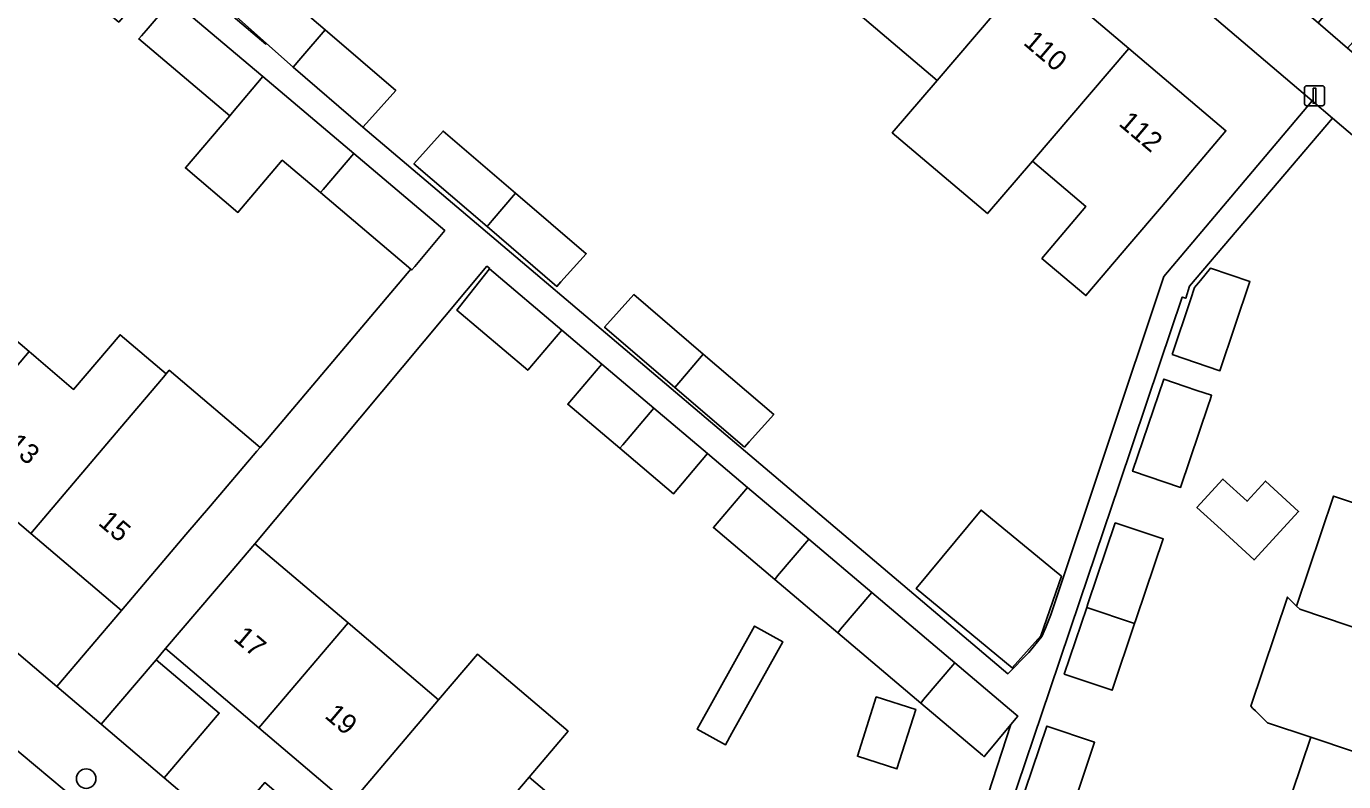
# Model space of a CAD drawing. Extents: x 162523 to 163266, y 381230 to 382050.
# Drawn here: x 163155.8 to 163221.9, y 381622.8 to 381660.7 of the extents above; entities that cross this region are included whole.
import ezdxf

# ---------------------------------------------------------------- set-up
doc = ezdxf.new("R2010")
doc.units = 0
for name, color, linetype in [('IMGEO_Boom', 7, 'Continuous'), ('IMGEO_Erf', 7, 'Continuous'), ('IMGEO_Grasland_overig', 7, 'Continuous'), ('IMGEO_Lichtmast', 7, 'Continuous'), ('IMGEO_Pand', 7, 'Continuous'), ('IMGEO_Pand_nummerreeks', 7, 'Continuous'), ('IMGEO_Rijbaan_lokaal_open', 7, 'Continuous'), ('IMGEO_Voetpad_open', 7, 'Continuous')]:
    doc.layers.add(name, color=color, linetype=linetype)

msp = doc.modelspace()

# ---------------------------------------------------------------- linework, layer by layer
at = {"layer": 'IMGEO_Boom'}
msp.add_circle((163158.816, 381622.902), 0.489, dxfattribs=at)
at = {"layer": 'IMGEO_Erf'}
for points in [[(163140.97, 381682.758), (163159.202, 381667.12), (163167.841, 381659.784), (163167.869, 381659.815), (163165.748, 381661.71), (163167.33, 381663.48), (163170.81, 381660.497), (163174.354, 381657.457), (163173.044, 381655.991), (163172.708, 381655.616), (163205.068, 381628.172), (163206.134, 381629.238), (163206.785, 381630.042), (163206.97, 381630.457), (163207.227, 381631.126), (163212.9, 381648.115), (163220.342, 381656.94), (163142.194, 381723.423)], [(163151.406, 381648.209), (163155.954, 381644.343), (163158.186, 381642.446), (163160.518, 381645.191), (163162.834, 381643.222), (163162.99, 381643.405), (163167.545, 381639.532), (163175.12, 381648.487), (163170.58, 381652.326), (163168.654, 381653.955), (163166.431, 381651.337), (163163.797, 381653.565), (163166.019, 381656.183), (163161.457, 381660.042), (163161.596, 381660.206), (163161.82, 381660.47), (163163.132, 381662.014), (163162.131, 381662.862), (163160.455, 381660.889), (163156.896, 381663.899), (163153.342, 381666.904)], [(163206.364, 381663.627), (163211.148, 381659.567), (163216.021, 381655.432), (163212.786, 381651.621), (163211.199, 381649.751), (163208.995, 381647.155), (163206.79, 381649.026), (163208.993, 381651.623), (163206.306, 381653.903), (163204.053, 381651.276), (163199.275, 381655.331), (163201.522, 381657.963), (163196.777, 381661.991)], [(163237.57, 381642.272), (163221.374, 381656.062), (163214.196, 381647.625), (163214.001, 381647.024), (163213.833, 381647.081), (163212.71, 381643.748), (163210.663, 381637.676), (163208.69, 381631.823), (163207.189, 381627.369), (163205.166, 381621.366)], [(163199.319, 381607.452), (163205.221, 381625.613), (163203.918, 381624.045), (163203.885, 381624.005), (163203.802, 381624.076), (163200.704, 381626.699), (163196.538, 381630.229), (163193.375, 381632.907), (163190.301, 381635.511), (163192.013, 381637.526), (163190.008, 381639.224), (163188.297, 381637.209), (163185.603, 381639.491), (163182.989, 381641.705), (163184.7, 381643.721), (163182.692, 381645.421), (163180.982, 381643.406), (163177.413, 381646.429), (163177.549, 381646.6), (163179.062, 381648.496), (163179.074, 381648.511), (163178.931, 381648.633), (163167.279, 381634.698), (163171.959, 381630.718), (163176.507, 381626.851), (163178.456, 381629.146), (163183.004, 381625.278), (163181.055, 381622.983), (163185.603, 381619.116)], [(163151.263, 381632.684), (163157.339, 381627.523), (163160.588, 381631.345), (163156.035, 381635.214), (163151.486, 381639.08)], [(163220.278, 381624.983), (163218.109, 381625.71), (163217.509, 381626.301), (163217.378, 381626.43), (163217.269, 381626.537), (163219.109, 381632.022), (163219.218, 381631.915), (163219.571, 381631.567), (163221.424, 381637.086), (163223.462, 381636.403)], [(163218.394, 381619.371), (163220.278, 381624.983)]]:
    msp.add_lwpolyline(points, dxfattribs=at)
for points in [[(163183.914, 381649.259), (163182.647, 381647.842), (163182.447, 381647.618), (163178.937, 381650.628), (163175.265, 381653.776), (163176.733, 381655.417), (163180.368, 381652.301)], [(163213.316, 381644.197), (163214.242, 381646.943), (163214.452, 381647.569), (163214.743, 381647.923), (163215.242, 381648.531), (163217.229, 381647.861), (163215.721, 381643.386)], [(163193.323, 381641.191), (163192.098, 381639.82), (163191.856, 381639.55), (163188.362, 381642.546), (163184.835, 381645.57), (163186.303, 381647.211), (163189.79, 381644.22)], [(163213.747, 381637.529), (163211.34, 381638.336), (163212.899, 381642.961), (163213.97, 381642.6), (163214.563, 381642.4), (163215.304, 381642.15), (163215.226, 381641.918), (163215.15, 381641.691)], [(163215.775, 381635.411), (163214.567, 381636.522), (163215.874, 381637.943), (163217.081, 381636.832), (163218.008, 381637.84), (163219.671, 381636.312), (163217.437, 381633.883)], [(163207.411, 381633.352), (163207.761, 381633.063), (163206.733, 381630.076), (163205.297, 381628.462), (163200.477, 381632.448), (163203.737, 381636.391)], [(163211.441, 381630.688), (163210.312, 381627.339), (163207.907, 381628.149), (163209.034, 381631.494), (163209.099, 381631.686), (163210.467, 381635.745), (163212.874, 381634.938), (163211.54, 381630.983), (163211.506, 381630.88)], [(163192.366, 381630.559), (163193.789, 381629.764), (163191.23, 381625.182), (163190.902, 381624.596), (163189.479, 381625.391)], [(163176.585, 381617.719), (163172.036, 381621.586), (163167.487, 381625.452), (163162.803, 381629.433), (163162.328, 381628.874), (163165.493, 381626.194), (163162.731, 381622.942), (163165.78, 381620.352), (163167.777, 381622.704), (163173.818, 381617.55), (163171.832, 381615.212), (163174.881, 381612.622), (163176.901, 381615.001), (163182.949, 381609.858), (163180.931, 381607.482), (163184.651, 381604.323), (163186.72, 381602.564), (163191.624, 381598.399), (163194.85, 381602.194), (163190.231, 381606.12), (163185.682, 381609.986), (163181.133, 381613.853)], [(163198.474, 381627.005), (163200.454, 381626.376), (163199.508, 381623.394), (163197.528, 381624.023)], [(163207.981, 381620.422), (163206.547, 381616.169), (163206.45, 381615.881), (163204.044, 381616.689), (163204.172, 381617.067), (163205.574, 381621.229), (163207.027, 381625.539), (163209.433, 381624.732)]]:
    msp.add_lwpolyline(points, close=True, dxfattribs=at)
at = {"layer": 'IMGEO_Grasland_overig'}
msp.add_lwpolyline([(163165.493, 381626.194), (163162.328, 381628.874), (163159.568, 381625.629), (163162.731, 381622.942)], close=True, dxfattribs=at)
at = {"layer": 'IMGEO_Lichtmast'}
for p, q in [((163220.072, 381657.694), (163220.862, 381657.694)), ((163220.862, 381657.694), (163220.072, 381657.694)), ((163219.972, 381656.794), (163219.972, 381657.594)), ((163219.972, 381657.594), (163219.972, 381656.794)), ((163220.962, 381657.594), (163220.962, 381656.794)), ((163220.962, 381656.794), (163220.962, 381657.594)), ((163220.862, 381656.694), (163220.072, 381656.694)), ((163220.072, 381656.694), (163220.862, 381656.694))]:
    msp.add_line(p, q, dxfattribs=at)
msp.add_lwpolyline([(163220.392, 381657.569), (163220.542, 381657.569), (163220.542, 381656.819), (163220.392, 381656.819), (163220.392, 381657.569)], dxfattribs=at)
for centre, start, end in [((163220.072, 381657.594), 90, 180), ((163220.072, 381657.594), 90, 180), ((163220.862, 381657.594), 0, 90), ((163220.862, 381657.594), 360, 90), ((163220.072, 381656.794), 180, 270), ((163220.072, 381656.794), 180, 270), ((163220.862, 381656.794), 270, 0), ((163220.862, 381656.794), 270, 0)]:
    msp.add_arc(centre, 0.1, start, end, dxfattribs=at)
at = {"layer": 'IMGEO_Pand'}
for points in [[(163196.777, 381661.991), (163201.522, 381657.963), (163206.364, 381663.627), (163201.621, 381667.653)], [(163206.306, 381653.903), (163211.148, 381659.567), (163206.364, 381663.627), (163201.522, 381657.963), (163199.275, 381655.331), (163204.053, 381651.276)], [(163167.869, 381659.815), (163169.205, 381658.62), (163169.595, 381659.076), (163170.81, 381660.497), (163167.33, 381663.48), (163165.748, 381661.71)], [(163163.132, 381662.014), (163161.82, 381660.47), (163161.596, 381660.206), (163161.457, 381660.042), (163166.019, 381656.183), (163166.159, 381656.348), (163167.691, 381658.152)], [(163170.81, 381660.497), (163169.595, 381659.076), (163169.205, 381658.62), (163172.708, 381655.616), (163173.044, 381655.991), (163174.354, 381657.457)], [(163206.306, 381653.903), (163208.993, 381651.623), (163206.79, 381649.026), (163208.995, 381647.155), (163211.199, 381649.751), (163212.786, 381651.621), (163216.021, 381655.432), (163211.148, 381659.567)], [(163167.691, 381658.152), (163166.159, 381656.348), (163166.019, 381656.183), (163163.797, 381653.565), (163166.431, 381651.337), (163168.654, 381653.955), (163170.58, 381652.326), (163170.72, 381652.49), (163172.249, 381654.291)], [(163178.937, 381650.628), (163179.195, 381650.929), (163180.368, 381652.301), (163176.733, 381655.417), (163175.265, 381653.776)], [(163172.249, 381654.291), (163170.72, 381652.49), (163170.58, 381652.326), (163175.12, 381648.487), (163175.167, 381648.447), (163175.305, 381648.613), (163176.813, 381650.426)], [(163180.368, 381652.301), (163179.195, 381650.929), (163178.937, 381650.628), (163182.447, 381647.618), (163182.647, 381647.842), (163183.914, 381649.259)], [(163179.062, 381648.496), (163177.549, 381646.6), (163177.413, 381646.429), (163180.982, 381643.406), (163182.692, 381645.421)], [(163213.316, 381644.197), (163215.721, 381643.386), (163217.229, 381647.861), (163215.242, 381648.531), (163214.743, 381647.923), (163214.452, 381647.569), (163214.242, 381646.943)], [(163146.937, 381642.946), (163151.486, 381639.08), (163155.954, 381644.343), (163151.406, 381648.209)], [(163188.362, 381642.546), (163188.66, 381642.896), (163189.79, 381644.22), (163186.303, 381647.211), (163184.835, 381645.57)], [(163162.834, 381643.222), (163160.518, 381645.191), (163158.186, 381642.446), (163155.954, 381644.343), (163151.486, 381639.08), (163156.035, 381635.214), (163160.503, 381640.476), (163162.699, 381643.063)], [(163184.7, 381643.721), (163182.989, 381641.705), (163185.603, 381639.491), (163185.746, 381639.66), (163187.314, 381641.506)], [(163189.79, 381644.22), (163188.66, 381642.896), (163188.362, 381642.546), (163191.856, 381639.55), (163192.098, 381639.82), (163193.323, 381641.191)], [(163162.834, 381643.222), (163162.699, 381643.063), (163160.503, 381640.476), (163156.035, 381635.214), (163160.588, 381631.345), (163163.826, 381635.156), (163165.057, 381636.604), (163167.39, 381639.348), (163167.545, 381639.532), (163162.99, 381643.405)], [(163213.97, 381642.6), (163212.899, 381642.961), (163211.34, 381638.336), (163213.747, 381637.529), (163215.15, 381641.691), (163215.226, 381641.918), (163215.304, 381642.15), (163214.563, 381642.4)], [(163190.008, 381639.224), (163187.314, 381641.506), (163185.746, 381639.66), (163185.603, 381639.491), (163188.297, 381637.209)], [(163217.081, 381636.832), (163215.874, 381637.943), (163214.567, 381636.522), (163215.775, 381635.411), (163217.437, 381633.883), (163219.671, 381636.312), (163218.008, 381637.84)], [(163192.013, 381637.526), (163190.301, 381635.511), (163193.375, 381632.907), (163193.52, 381633.078), (163195.086, 381634.923)], [(163230.567, 381634.022), (163224.045, 381636.208), (163223.462, 381636.403), (163221.424, 381637.086), (163219.571, 381631.567), (163219.73, 381631.411), (163222.161, 381630.596), (163228.685, 381628.409)], [(163200.477, 381632.448), (163205.297, 381628.462), (163206.733, 381630.076), (163207.761, 381633.063), (163207.411, 381633.352), (163203.737, 381636.391)], [(163209.034, 381631.494), (163211.441, 381630.688), (163211.506, 381630.88), (163211.54, 381630.983), (163212.874, 381634.938), (163210.467, 381635.745), (163209.099, 381631.686)], [(163167.487, 381625.452), (163171.959, 381630.718), (163167.279, 381634.698), (163166.042, 381633.243), (163162.803, 381629.433)], [(163195.086, 381634.923), (163193.52, 381633.078), (163193.375, 381632.907), (163196.538, 381630.229), (163196.683, 381630.4), (163198.248, 381632.244)], [(163198.248, 381632.244), (163196.683, 381630.4), (163196.538, 381630.229), (163200.704, 381626.699), (163200.85, 381626.871), (163202.416, 381628.714)], [(163228.685, 381628.409), (163222.161, 381630.596), (163219.73, 381631.411), (163219.571, 381631.567), (163219.218, 381631.915), (163219.109, 381632.022), (163217.269, 381626.537), (163217.378, 381626.43), (163217.509, 381626.301), (163218.109, 381625.71), (163220.278, 381624.983), (163226.804, 381622.796)], [(163211.441, 381630.688), (163209.034, 381631.494), (163207.907, 381628.149), (163210.312, 381627.339)], [(163167.487, 381625.452), (163172.036, 381621.586), (163176.507, 381626.851), (163171.959, 381630.718)], [(163189.479, 381625.391), (163190.902, 381624.596), (163191.23, 381625.182), (163193.789, 381629.764), (163192.366, 381630.559)], [(163181.055, 381622.983), (163183.004, 381625.278), (163178.456, 381629.146), (163176.507, 381626.851), (163172.036, 381621.586), (163176.585, 381617.719)], [(163202.416, 381628.714), (163200.85, 381626.871), (163200.704, 381626.699), (163203.802, 381624.076), (163203.885, 381624.005), (163203.918, 381624.045), (163205.221, 381625.613), (163205.574, 381626.039), (163205.154, 381626.394)], [(163197.528, 381624.023), (163199.508, 381623.394), (163200.454, 381626.376), (163198.474, 381627.005)], [(163205.574, 381621.229), (163207.448, 381620.601), (163207.595, 381620.552), (163207.981, 381620.422), (163209.433, 381624.732), (163207.027, 381625.539)], [(163220.278, 381624.983), (163218.394, 381619.371), (163224.923, 381617.183), (163226.804, 381622.796)], [(163185.603, 381619.116), (163181.055, 381622.983), (163176.585, 381617.719), (163181.133, 381613.853)]]:
    msp.add_lwpolyline(points, close=True, dxfattribs=at)
at = {"layer": 'IMGEO_Rijbaan_lokaal_open'}
msp.add_lwpolyline([(163155.947, 381618.976), (163158.315, 381621.734), (163158.107, 381621.91), (163158.194, 381622.012), (163157.973, 381622.156), (163157.707, 381622.339), (163154.829, 381624.748), (163154.677, 381624.892), (163154.343, 381625.343), (163154.207, 381625.235), (163154.129, 381625.302), (163151.866, 381622.506), (163152.117, 381622.4), (163152.423, 381622.195), (163155.719, 381619.322), (163155.878, 381619.093)], close=True, dxfattribs=at)
at = {"layer": 'IMGEO_Voetpad_open'}
for points in [[(163145.337, 381726.7), (163142.194, 381723.423), (163220.342, 381656.94), (163221.374, 381656.062), (163237.57, 381642.272), (163241.66, 381639.009), (163250.252, 381632.117), (163250.367, 381633.129)], [(163237.947, 381646.091), (163227.167, 381655.314), (163222.131, 381659.586), (163220.653, 381660.859), (163207.022, 381672.435), (163206.696, 381672.73), (163205.174, 381674.003), (163201.925, 381676.775), (163191.471, 381685.659), (163189.947, 381686.961), (163186.391, 381689.994), (163176.258, 381698.624), (163174.752, 381699.935), (163164.938, 381708.239)], [(163159.568, 381625.629), (163157.339, 381627.523), (163151.263, 381632.684), (163148.238, 381635.254), (163139.137, 381642.985), (163136.111, 381645.555), (163133.063, 381648.145), (163127.011, 381653.286), (163123.962, 381655.875), (163120.755, 381658.6), (163119.655, 381659.534), (163118.125, 381660.834), (163117.58, 381661.297), (163106.497, 381670.706), (163101.218, 381675.181), (163100.456, 381675.828), (163098.283, 381673.302)], [(163205.166, 381621.366), (163207.189, 381627.369), (163208.69, 381631.823), (163210.663, 381637.676), (163212.71, 381643.748), (163213.833, 381647.081), (163214.001, 381647.024), (163214.196, 381647.625), (163221.374, 381656.062), (163220.342, 381656.94), (163212.9, 381648.115), (163207.227, 381631.126), (163206.97, 381630.457), (163206.785, 381630.042), (163206.134, 381629.238), (163205.068, 381628.172), (163172.708, 381655.616), (163169.205, 381658.62), (163167.869, 381659.815), (163167.841, 381659.784), (163159.202, 381667.12)], [(163163.132, 381662.014), (163167.691, 381658.152), (163172.249, 381654.291), (163176.813, 381650.426), (163175.305, 381648.613), (163175.167, 381648.447), (163175.12, 381648.487), (163167.545, 381639.532), (163167.39, 381639.348), (163165.057, 381636.604), (163163.826, 381635.156), (163160.588, 381631.345), (163157.339, 381627.523), (163159.568, 381625.629), (163162.328, 381628.874), (163162.803, 381629.433), (163166.042, 381633.243), (163167.279, 381634.698), (163178.931, 381648.633), (163179.074, 381648.511), (163179.062, 381648.496), (163182.692, 381645.421), (163184.7, 381643.721), (163187.314, 381641.506), (163190.008, 381639.224), (163192.013, 381637.526), (163195.086, 381634.923), (163198.248, 381632.244), (163202.416, 381628.714), (163205.154, 381626.394), (163205.574, 381626.039), (163205.221, 381625.613), (163199.319, 381607.452)], [(163153.965, 381627.453), (163154.089, 381626.115), (163154.343, 381625.343), (163154.677, 381624.892), (163154.829, 381624.748), (163157.707, 381622.339), (163157.973, 381622.156), (163158.194, 381622.012)], [(163204.493, 381582.322), (163215.616, 381577.85), (163215.721, 381578.005), (163218.125, 381581.561), (163213.504, 381583.11), (163206.962, 381585.303), (163194.728, 381595.768), (163194.315, 381596.121), (163192.786, 381597.412), (163192.617, 381597.555), (163191.624, 381598.399), (163186.72, 381602.564), (163184.651, 381604.323), (163180.931, 381607.482), (163174.881, 381612.622), (163171.832, 381615.212), (163165.78, 381620.352), (163162.731, 381622.942), (163159.568, 381625.629)]]:
    msp.add_lwpolyline(points, dxfattribs=at)
msp.add_lwpolyline([(163220.653, 381660.859), (163222.131, 381659.586), (163226.164, 381664.173), (163224.603, 381665.503), (163222.401, 381662.914), (163220.912, 381661.164)], close=True, dxfattribs=at)

# ---------------------------------------------------------------- texts
at = {"layer": 'IMGEO_Pand_nummerreeks'}
for s, rotation, p in [('110', 319.67952, (163205.805, 381659.799)), ('112', 319.67952, (163210.59, 381655.739)), ('13', 319.64085, (163154.8, 381639.57)), ('15', 319.64085, (163159.373, 381635.685)), ('17', 319.63645, (163166.163, 381629.884)), ('19', 319.63645, (163170.741, 381625.993))]:
    msp.add_text(s, height=1, rotation=rotation, dxfattribs=at).set_placement(p)

doc.saveas('drawing.dxf')
